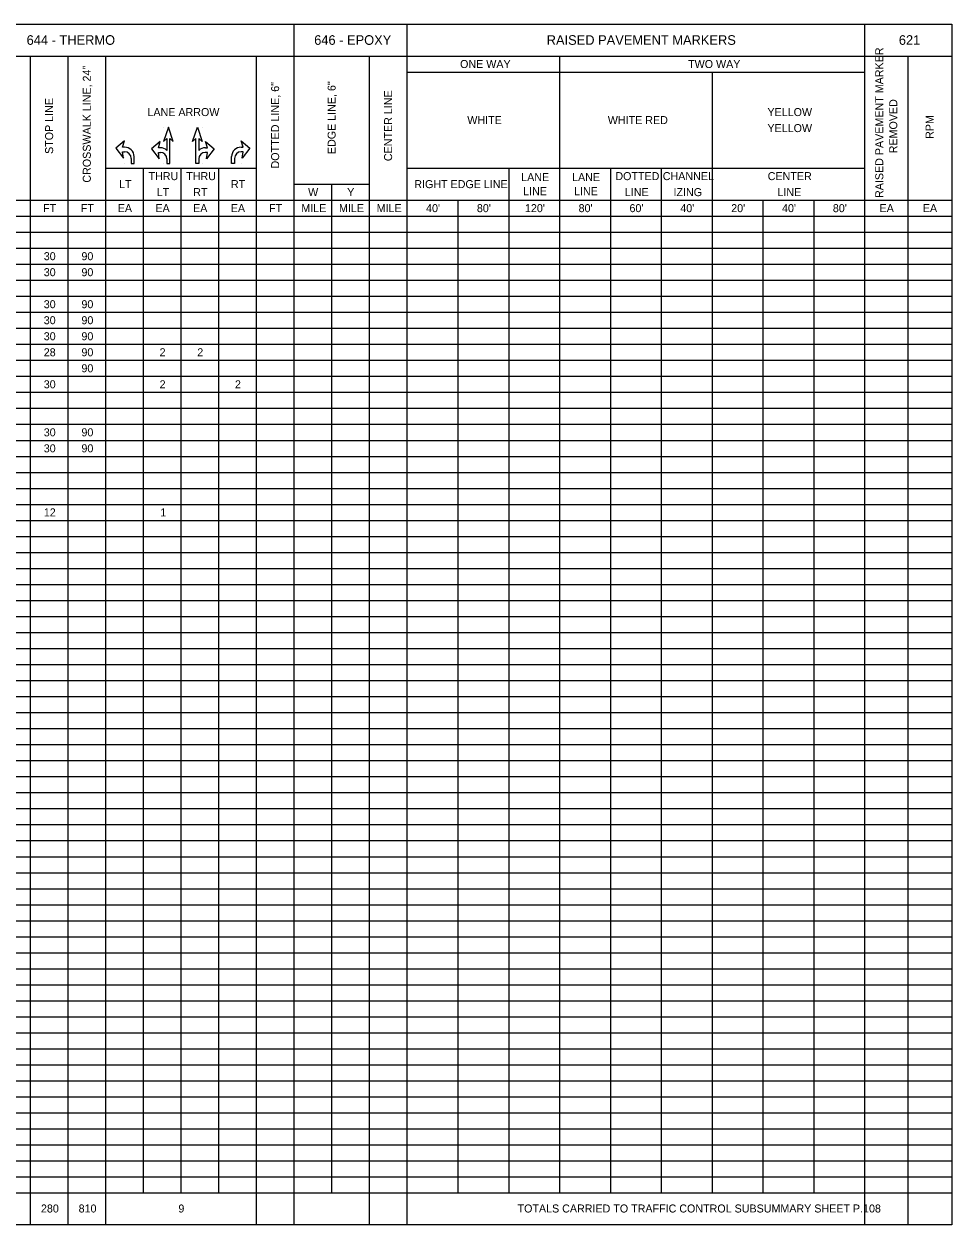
# Model space of a CAD drawing. Extents: x 12522 to 13018, y 1124 to 1902.
# Drawn here: x 12887.42 to 12903.65, y 1732.23 to 1753.23 of the extents above; entities that cross this region are included whole.
import ezdxf

# ---------------------------------------------------------------- set-up
doc = ezdxf.new("R2010")
doc.units = 0
for name, color, linetype in [('MT_X_Cells', 7, 'Continuous'), ('PM_P_Cells', 7, 'Continuous'), ('SC_Scratch1', 7, 'Continuous'), ('SH_Data', 7, 'Continuous'), ('SH_Text', 7, 'Continuous')]:
    doc.layers.add(name, color=color, linetype=linetype)

msp = doc.modelspace()

# ---------------------------------------------------------------- linework, layer by layer
at = {"layer": 'MT_X_Cells'}
for p, q in [((12889.941, 1751.422), (12889.854, 1751.172)), ((12889.858, 1751.422), (12889.858, 1751.422)), ((12890.028, 1751.172), (12889.941, 1751.422)), ((12890.362, 1751.172), (12890.449, 1751.422)), ((12890.449, 1751.422), (12890.535, 1751.172)), ((12890.532, 1751.422), (12890.532, 1751.422)), ((12889.854, 1751.172), (12889.916, 1751.222)), ((12889.966, 1750.785), (12889.966, 1751.222)), ((12889.966, 1751.222), (12890.028, 1751.172)), ((12890.424, 1751.222), (12890.362, 1751.172)), ((12890.424, 1750.785), (12890.424, 1751.222)), ((12890.535, 1751.172), (12890.474, 1751.222)), ((12889.799, 1751.175), (12889.649, 1751.047)), ((12889.649, 1751.047), (12889.783, 1750.871)), ((12889.766, 1751.063), (12889.799, 1751.175)), ((12889.799, 1751.063), (12889.766, 1751.063)), ((12889.783, 1750.871), (12889.766, 1750.983)), ((12889.766, 1750.983), (12889.801, 1750.983)), ((12890.624, 1750.983), (12890.588, 1750.983)), ((12890.624, 1751.063), (12890.59, 1751.175)), ((12890.59, 1751.175), (12890.74, 1751.047)), ((12890.59, 1751.063), (12890.624, 1751.063)), ((12890.74, 1751.047), (12890.607, 1750.871)), ((12890.607, 1750.871), (12890.624, 1750.983)), ((12889.858, 1750.785), (12889.858, 1750.785)), ((12889.916, 1750.868), (12889.916, 1750.785)), ((12889.916, 1750.785), (12889.966, 1750.785)), ((12890.474, 1750.785), (12890.424, 1750.785)), ((12890.474, 1750.868), (12890.474, 1750.785)), ((12890.532, 1750.785), (12890.532, 1750.785))]:
    msp.add_line(p, q, dxfattribs=at)
for points in [[(12889.916, 1751.222), (12889.916, 1751.017)], [(12890.474, 1751.222), (12890.474, 1751.017)]]:
    msp.add_lwpolyline(points, dxfattribs=at)
for centre, radius, start, end in [((12889.802, 1750.899), 0.164, 45.9534, 90.9085), ((12889.801, 1750.868), 0.115, 360, 90), ((12890.588, 1750.899), 0.164, 89.0915, 134.0466), ((12890.588, 1750.868), 0.115, 90, 180)]:
    msp.add_arc(centre, radius, start, end, dxfattribs=at)
at = {"layer": 'PM_P_Cells'}
for p, q in [((12889.175, 1751.185), (12889.025, 1751.057)), ((12889.025, 1751.057), (12889.159, 1750.881)), ((12889.142, 1751.073), (12889.175, 1751.185)), ((12889.175, 1751.073), (12889.142, 1751.073)), ((12889.159, 1750.881), (12889.142, 1750.993)), ((12889.142, 1750.993), (12889.177, 1750.993)), ((12889.175, 1751.185), (12889.175, 1751.185)), ((12891.248, 1750.993), (12891.213, 1750.993)), ((12891.214, 1751.185), (12891.214, 1751.185)), ((12891.248, 1751.073), (12891.214, 1751.185)), ((12891.214, 1751.185), (12891.364, 1751.057)), ((12891.214, 1751.073), (12891.248, 1751.073)), ((12891.364, 1751.057), (12891.231, 1750.881)), ((12891.231, 1750.881), (12891.248, 1750.993)), ((12889.175, 1750.785), (12889.175, 1750.785)), ((12889.292, 1750.878), (12889.292, 1750.785)), ((12889.292, 1750.785), (12889.342, 1750.785)), ((12889.342, 1750.785), (12889.342, 1750.909)), ((12891.048, 1750.785), (12891.048, 1750.909)), ((12891.098, 1750.785), (12891.048, 1750.785)), ((12891.098, 1750.878), (12891.098, 1750.785)), ((12891.214, 1750.785), (12891.214, 1750.785))]:
    msp.add_line(p, q, dxfattribs=at)
for centre, radius, start, end in [((12889.178, 1750.909), 0.164, 0, 90.9085), ((12889.177, 1750.878), 0.115, 0, 90), ((12891.212, 1750.909), 0.164, 89.0915, 180), ((12891.213, 1750.878), 0.115, 90, 180)]:
    msp.add_arc(centre, radius, start, end, dxfattribs=at)
at = {"layer": 'SC_Scratch1'}
msp.add_lwpolyline([(12873.148, 1753.227), (12903.648, 1753.227), (12903.648, 1732.227), (12873.148, 1732.227)], close=True, dxfattribs=at)
at = {"layer": 'SH_Data'}
for p, q in [((12892.138, 1753.227), (12892.138, 1732.243)), ((12894.115, 1753.227), (12894.115, 1732.243)), ((12902.12, 1753.227), (12902.12, 1732.243)), ((12873.148, 1752.667), (12903.635, 1752.667)), ((12887.527, 1752.667), (12887.527, 1732.243)), ((12888.185, 1752.667), (12888.185, 1732.243)), ((12888.844, 1752.667), (12888.844, 1732.243)), ((12891.48, 1752.667), (12891.48, 1732.243)), ((12893.456, 1752.667), (12893.456, 1732.243)), ((12896.783, 1752.667), (12896.783, 1732.787)), ((12902.877, 1752.667), (12902.877, 1732.243)), ((12894.115, 1752.387), (12902.12, 1752.387)), ((12899.451, 1752.387), (12899.451, 1732.787)), ((12888.844, 1750.707), (12891.48, 1750.707)), ((12889.503, 1750.707), (12889.503, 1732.787)), ((12890.162, 1750.707), (12890.162, 1732.787)), ((12890.821, 1750.707), (12890.821, 1732.787)), ((12894.115, 1750.707), (12902.12, 1750.707)), ((12895.894, 1750.707), (12895.894, 1732.787)), ((12897.673, 1750.707), (12897.673, 1732.787)), ((12898.562, 1750.707), (12898.562, 1732.787)), ((12892.138, 1750.427), (12893.456, 1750.427)), ((12892.797, 1750.427), (12892.797, 1732.787)), ((12880.477, 1750.147), (12903.635, 1750.147)), ((12895.004, 1750.147), (12895.004, 1732.787)), ((12900.341, 1750.147), (12900.341, 1732.787)), ((12901.23, 1750.147), (12901.23, 1732.787)), ((12873.148, 1749.867), (12903.635, 1749.867)), ((12873.148, 1749.587), (12903.635, 1749.587)), ((12873.148, 1749.307), (12903.635, 1749.307)), ((12873.148, 1749.027), (12903.635, 1749.027)), ((12873.148, 1748.747), (12903.635, 1748.747)), ((12873.148, 1748.467), (12903.635, 1748.467)), ((12873.148, 1748.187), (12903.635, 1748.187)), ((12873.148, 1747.907), (12903.635, 1747.907)), ((12873.148, 1747.627), (12903.635, 1747.627)), ((12873.148, 1747.347), (12903.635, 1747.347)), ((12873.148, 1747.067), (12903.635, 1747.067)), ((12873.148, 1746.787), (12903.635, 1746.787)), ((12873.148, 1746.507), (12903.635, 1746.507)), ((12873.148, 1746.227), (12903.635, 1746.227)), ((12873.148, 1745.947), (12903.635, 1745.947)), ((12873.148, 1745.667), (12903.635, 1745.667)), ((12873.148, 1745.387), (12903.635, 1745.387)), ((12873.148, 1745.107), (12903.635, 1745.107)), ((12873.148, 1744.827), (12903.635, 1744.827)), ((12873.148, 1744.547), (12903.635, 1744.547)), ((12873.148, 1744.267), (12903.635, 1744.267)), ((12873.148, 1743.987), (12903.635, 1743.987)), ((12873.148, 1743.707), (12903.635, 1743.707)), ((12873.148, 1743.427), (12903.635, 1743.427)), ((12873.148, 1743.147), (12903.635, 1743.147)), ((12873.148, 1742.867), (12903.635, 1742.867)), ((12873.148, 1742.587), (12903.635, 1742.587)), ((12873.148, 1742.307), (12903.635, 1742.307)), ((12873.148, 1742.027), (12903.635, 1742.027)), ((12873.148, 1741.747), (12903.635, 1741.747)), ((12873.148, 1741.467), (12903.635, 1741.467)), ((12873.148, 1741.187), (12903.635, 1741.187)), ((12873.148, 1740.907), (12903.635, 1740.907)), ((12873.148, 1740.627), (12903.635, 1740.627)), ((12873.148, 1740.347), (12903.635, 1740.347)), ((12873.148, 1740.067), (12903.635, 1740.067)), ((12873.148, 1739.787), (12903.635, 1739.787)), ((12873.148, 1739.507), (12903.635, 1739.507)), ((12873.148, 1739.227), (12903.635, 1739.227)), ((12873.148, 1738.947), (12903.635, 1738.947)), ((12873.148, 1738.667), (12903.635, 1738.667)), ((12873.148, 1738.387), (12903.635, 1738.387)), ((12873.148, 1738.107), (12903.635, 1738.107)), ((12873.148, 1737.827), (12903.635, 1737.827)), ((12873.148, 1737.547), (12903.635, 1737.547)), ((12873.148, 1737.267), (12903.635, 1737.267)), ((12873.148, 1736.987), (12903.635, 1736.987)), ((12873.148, 1736.707), (12903.635, 1736.707)), ((12873.148, 1736.427), (12903.635, 1736.427)), ((12873.148, 1736.147), (12903.635, 1736.147)), ((12873.148, 1735.867), (12903.635, 1735.867)), ((12873.148, 1735.587), (12903.635, 1735.587)), ((12873.148, 1735.307), (12903.635, 1735.307)), ((12873.148, 1735.027), (12903.635, 1735.027)), ((12873.148, 1734.747), (12903.635, 1734.747)), ((12873.148, 1734.467), (12903.635, 1734.467)), ((12873.148, 1734.187), (12903.635, 1734.187)), ((12873.148, 1733.907), (12903.635, 1733.907)), ((12873.148, 1733.627), (12903.635, 1733.627)), ((12873.148, 1733.347), (12903.635, 1733.347)), ((12873.148, 1733.067), (12903.635, 1733.067)), ((12873.148, 1732.787), (12903.635, 1732.787))]:
    msp.add_line(p, q, dxfattribs=at)

# ---------------------------------------------------------------- texts
at = {"layer": 'SH_Text'}
for s, height, p in [('644 - THERMO', 0.168, (12887.462, 1752.863)), ('646 - EPOXY', 0.168, (12892.492, 1752.863)), ('RAISED PAVEMENT MARKERS', 0.168, (12896.559, 1752.863)), ('621', 0.168, (12902.718, 1752.863)), ('ONE WAY', 0.14, (12895.044, 1752.457)), ('TWO WAY', 0.14, (12899.032, 1752.457)), ('LANE ARROW', 0.14, (12889.576, 1751.617)), ('WHITE', 0.14, (12895.17, 1751.477)), ('WHITE RED', 0.14, (12897.628, 1751.477)), ('YELLOW', 0.14, (12900.42, 1751.617)), ('YELLOW', 0.14, (12900.42, 1751.337)), ('THRU', 0.14, (12889.595, 1750.497)), ('THRU', 0.14, (12890.254, 1750.497)), ('LANE  ', 0.14, (12896.113, 1750.479)), ('LANE  ', 0.14, (12897.003, 1750.479)), ('DOTTED', 0.14, (12897.76, 1750.497)), ('CHANNEL', 0.14, (12898.589, 1750.497)), ('CENTER', 0.14, (12900.425, 1750.497)), ('LT', 0.14, (12889.079, 1750.357)), ('LT', 0.14, (12889.738, 1750.217)), ('RT', 0.14, (12890.377, 1750.217)), ('RT', 0.14, (12891.036, 1750.357)), ('W', 0.14, (12892.386, 1750.217)), ('Y', 0.14, (12893.069, 1750.217)), ('RIGHT EDGE LINE', 0.14, (12894.243, 1750.357)), ('LINE', 0.14, (12896.147, 1750.234)), ('LINE', 0.14, (12897.037, 1750.234)), ('LINE', 0.14, (12897.926, 1750.217)), ('IZING', 0.14, (12898.777, 1750.217)), ('LINE', 0.14, (12900.595, 1750.217)), ('FT', 0.14, (12887.75, 1749.937)), ('FT', 0.14, (12888.409, 1749.937)), ('EA', 0.14, (12889.056, 1749.937)), ('EA', 0.14, (12889.715, 1749.937)), ('EA', 0.14, (12890.374, 1749.937)), ('EA', 0.14, (12891.033, 1749.937)), ('FT', 0.14, (12891.703, 1749.937)), ('MILE', 0.14, (12892.267, 1749.937)), ('MILE', 0.14, (12892.926, 1749.937)), ('MILE', 0.14, (12893.585, 1749.937)), ("40'", 0.14, (12894.449, 1749.937)), ("80'", 0.14, (12895.338, 1749.937)), ("120'", 0.14, (12896.179, 1749.937)), ("80'", 0.14, (12897.117, 1749.937)), ("60'", 0.14, (12898.007, 1749.937)), ("40'", 0.14, (12898.896, 1749.937)), ("20'", 0.14, (12899.786, 1749.937)), ("40'", 0.14, (12900.675, 1749.937)), ("80'", 0.14, (12901.564, 1749.937)), ('EA', 0.14, (12902.381, 1749.937)), ('EA', 0.14, (12903.138, 1749.937)), ('30', 0.14, (12887.762, 1749.097)), ('90', 0.14, (12888.421, 1749.097)), ('30', 0.14, (12887.762, 1748.817)), ('90', 0.14, (12888.421, 1748.817)), ('30', 0.14, (12887.762, 1748.257)), ('90', 0.14, (12888.421, 1748.257)), ('30', 0.14, (12887.762, 1747.977)), ('90', 0.14, (12888.421, 1747.977)), ('30', 0.14, (12887.762, 1747.697)), ('90', 0.14, (12888.421, 1747.697)), ('28', 0.14, (12887.762, 1747.417)), ('90', 0.14, (12888.421, 1747.417)), ('2', 0.14, (12889.788, 1747.417)), ('2', 0.14, (12890.447, 1747.417)), ('90', 0.14, (12888.421, 1747.137)), ('30', 0.14, (12887.762, 1746.857)), ('2', 0.14, (12889.788, 1746.857)), ('2', 0.14, (12891.106, 1746.857)), ('30', 0.14, (12887.762, 1746.017)), ('90', 0.14, (12888.421, 1746.017)), ('30', 0.14, (12887.762, 1745.737)), ('90', 0.14, (12888.421, 1745.737)), ('12', 0.14, (12887.763, 1744.617)), ('1', 0.14, (12889.8, 1744.617)), ('280', 0.14, (12887.713, 1732.445)), ('810', 0.14, (12888.372, 1732.445)), ('9', 0.14, (12890.117, 1732.445)), ('TOTALS CARRIED TO TRAFFIC CONTROL SUBSUMMARY SHEET P.108', 0.14, (12896.049, 1732.445))]:
    msp.add_text(s, height=height, dxfattribs=at).set_placement(p)
for s, p in [('RAISED PAVEMENT MARKER ', (12902.446, 1750.185)), ('CROSSWALK LINE, 24"', (12888.585, 1750.453)), ('DOTTED LINE, 6"', (12891.879, 1750.7)), ('EDGE LINE, 6"', (12892.867, 1750.952)), ('CENTER LINE', (12893.855, 1750.829)), ('STOP LINE', (12887.926, 1750.955)), ('REMOVED', (12902.691, 1750.966)), ('RPM', (12903.326, 1751.218))]:
    msp.add_text(s, height=0.14, rotation=90, dxfattribs=at).set_placement(p)

doc.saveas('drawing.dxf')
